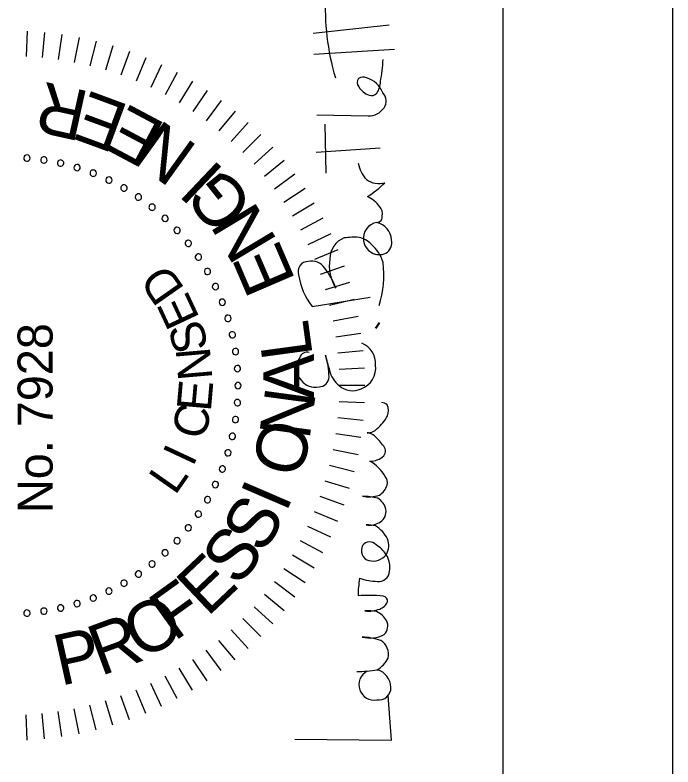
# Model space of a CAD drawing. Extents: x 9916 to 916479, y 6678 to 329942.
# Drawn here: x 916434.26 to 916471.17, y 329764.23 to 329806.42 of the extents above; entities that cross this region are included whole.
import ezdxf

# ---------------------------------------------------------------- set-up
doc = ezdxf.new("R2010")
doc.units = 0
for name, color, linetype in [('Border', 7, 'Continuous'), ('Default', 7, 'Continuous'), ('PLOT BOUNDARY', 7, 'Continuous')]:
    doc.layers.add(name, color=color, linetype=linetype)

# ---------------------------------------------------------------- blocks, each defined once
blk = doc.blocks.new('STAMP')
at = {"layer": 'Default'}
for p, q in [((-0.007955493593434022, 0.0011091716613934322), (-0.007387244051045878, 0.0011370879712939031)), ((0.007955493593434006, 0.0011091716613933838), (0.007387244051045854, 0.0011370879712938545)), ((-0.007926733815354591, 0.0007192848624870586), (-0.007360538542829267, 0.0007750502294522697)), ((0.007926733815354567, 0.0007192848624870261), (0.007360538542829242, 0.0007750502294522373)), ((-0.007878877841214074, 0.0003312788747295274), (-0.0073161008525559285, 0.00041475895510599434)), ((0.007878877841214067, 0.00033127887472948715), (0.00731610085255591, 0.0004147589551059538)), ((-0.007812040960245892, -5.391156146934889e-05), (-0.007254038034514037, 5.708212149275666e-05)), ((0.007812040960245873, -5.3911561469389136e-05), (0.007254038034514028, 5.7082121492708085e-05)), ((-0.0077263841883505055, -0.0004353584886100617), (-0.0071744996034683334, -0.00029711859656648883)), ((0.007726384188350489, -0.0004353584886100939), (0.0071744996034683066, -0.00029711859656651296)), ((-0.007622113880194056, -0.0008121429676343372), (-0.007077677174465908, -0.0006469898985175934)), ((0.0076221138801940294, -0.0008121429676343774), (0.007077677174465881, -0.0006469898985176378)), ((-0.00749948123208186, -0.0011833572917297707), (-0.0069638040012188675, -0.00099168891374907)), ((0.007499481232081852, -0.0011833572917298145), (0.006963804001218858, -0.0009916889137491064)), ((-0.007358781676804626, -0.0015481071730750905), (-0.006833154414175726, -0.001330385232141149)), ((0.007358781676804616, -0.0015481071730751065), (0.006833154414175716, -0.001330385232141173)), ((-0.007200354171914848, -0.0019055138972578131), (-0.006686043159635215, -0.0016622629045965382)), ((0.007200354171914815, -0.0019055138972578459), (0.006686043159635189, -0.0016622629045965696)), ((-0.007024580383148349, -0.0022547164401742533), (-0.0065228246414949, -0.001986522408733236)), ((0.0070245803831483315, -0.0022547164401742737), (0.006522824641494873, -0.001986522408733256)), ((-0.006831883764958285, -0.002594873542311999), (-0.006343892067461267, -0.0023023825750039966)), ((0.006831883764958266, -0.0025948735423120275), (0.006343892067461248, -0.002302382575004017)), ((-0.006622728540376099, -0.002925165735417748), (-0.0061496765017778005, -0.0026090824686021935)), ((0.006622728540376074, -0.002925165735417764), (0.006149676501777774, -0.0026090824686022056)), ((-0.00639761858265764, -0.0032447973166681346), (-0.005940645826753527, -0.0029058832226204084)), ((0.006397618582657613, -0.0032447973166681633), (0.005940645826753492, -0.0029058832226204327)), ((-0.006157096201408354, -0.003552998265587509), (-0.005717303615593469, -0.0031920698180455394)), ((0.006157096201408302, -0.0035529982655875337), (0.005717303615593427, -0.0031920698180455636)), ((-0.005901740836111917, -0.003849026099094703), (-0.005480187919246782, -0.0034669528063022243)), ((0.005901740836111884, -0.0038490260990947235), (0.005480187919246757, -0.0034669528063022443)), ((-0.0056321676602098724, -0.0041321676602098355), (-0.00522986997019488, -0.003729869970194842)), ((0.00563216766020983, -0.0041321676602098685), (0.0052298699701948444, -0.0037298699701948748)), ((-0.005349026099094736, -0.004401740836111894), (-0.004966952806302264, -0.003980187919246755)), ((0.005349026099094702, -0.004401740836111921), (0.004966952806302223, -0.003980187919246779)), ((-0.0050529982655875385, -0.004657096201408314), (-0.004692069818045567, -0.004217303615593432)), ((0.005052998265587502, -0.004657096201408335), (0.004692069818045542, -0.004217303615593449)), ((-0.004744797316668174, -0.0048976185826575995), (-0.004405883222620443, -0.004440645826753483)), ((0.004744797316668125, -0.0048976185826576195), (0.004405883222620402, -0.0044406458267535)), ((-0.0044251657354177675, -0.005122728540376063), (-0.004109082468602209, -0.004649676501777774)), ((0.004425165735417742, -0.00512272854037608), (0.004109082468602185, -0.004649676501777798)), ((-0.004094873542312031, -0.005331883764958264), (-0.0038023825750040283, -0.004843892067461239)), ((0.0040948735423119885, -0.005331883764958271), (0.003802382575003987, -0.004843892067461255)), ((-0.0037547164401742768, -0.005524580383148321), (-0.0034865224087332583, -0.005022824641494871)), ((0.0037547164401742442, -0.005524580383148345), (0.003486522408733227, -0.005022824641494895)), ((-0.003405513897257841, -0.005700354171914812), (-0.0031622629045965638, -0.0051860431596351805)), ((0.0034055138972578, -0.005700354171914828), (0.003162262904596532, -0.005186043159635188)), ((-0.003048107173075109, -0.005858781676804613), (-0.0028303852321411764, -0.005333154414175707)), ((0.003048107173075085, -0.005858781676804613), (0.002830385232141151, -0.005333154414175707)), ((0.00523613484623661, -0.005376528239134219), (0.005338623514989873, -0.0068089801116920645)), ((0.007439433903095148, -0.005319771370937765), (0.0075498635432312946, -0.007129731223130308)), ((0.007905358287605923, -0.005303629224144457), (0.008096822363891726, -0.007011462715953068)), ((-0.0026833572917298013, -0.005999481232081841), (-0.002491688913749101, -0.005463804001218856)), ((0.002683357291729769, -0.005999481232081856), (0.0024916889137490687, -0.005463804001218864)), ((-0.0023121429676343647, -0.006122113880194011), (-0.0021469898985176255, -0.005577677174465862)), ((-0.0019353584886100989, -0.006226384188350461), (-0.0017971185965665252, -0.005674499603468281)), ((0.0019353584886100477, -0.006226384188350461), (0.0017971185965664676, -0.005674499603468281)), ((0.0023121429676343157, -0.006122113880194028), (0.0021469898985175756, -0.005577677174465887)), ((0.004764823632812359, -0.005597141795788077), (0.005863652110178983, -0.005572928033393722)), ((-0.0015539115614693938, -0.006312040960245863), (-0.0014429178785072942, -0.005754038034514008)), ((-0.001168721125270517, -0.006378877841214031), (-0.0010852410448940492, -0.005816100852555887)), ((-0.0007807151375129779, -0.006426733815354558), (-0.0007249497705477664, -0.0058605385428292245)), ((-0.00039082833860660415, -0.006455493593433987), (-0.00036291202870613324, -0.005887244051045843)), ((-2.0539125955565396e-17, -0.006465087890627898), (-2.0539125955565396e-17, -0.005896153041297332)), ((0.0003908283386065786, -0.0064554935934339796), (0.0003629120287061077, -0.005887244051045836)), ((0.0007807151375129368, -0.006426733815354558), (0.0007249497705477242, -0.005860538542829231)), ((0.0011687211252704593, -0.006378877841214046), (0.0010852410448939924, -0.005816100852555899)), ((0.0015539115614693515, -0.006312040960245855), (0.0014429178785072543, -0.005754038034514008)), ((0.001282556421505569, -0.006716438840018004), (0.001411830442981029, -0.006805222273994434)), ((0.0012888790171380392, -0.0067038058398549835), (0.0014181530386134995, -0.006792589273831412))]:
    blk.add_line(p, q, dxfattribs=at)
for points in [[(-0.007938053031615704, -0.004895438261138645), (-0.007956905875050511, -0.007061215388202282), (-0.0069577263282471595, -0.006985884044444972)], [(0.0017747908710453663, -0.005281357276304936), (0.001982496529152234, -0.006583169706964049)], [(0.006077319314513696, -0.005389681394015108), (0.006050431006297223, -0.00653989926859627)]]:
    blk.add_lwpolyline(points, dxfattribs=at)
for centre, radius, start, end in [((-0.005106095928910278, 0.0011173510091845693), 7.111685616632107e-05, 94.28571428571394, 274.28571428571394), ((-0.005106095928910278, 0.0011173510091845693), 7.11168561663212e-05, 274.28571428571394, 94.28571428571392), ((0.005106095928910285, 0.0011173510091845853), 7.11168561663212e-05, 85.71428571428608, 265.71428571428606), ((0.005106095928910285, 0.0011173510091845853), 7.11168561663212e-05, 265.71428571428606, 85.71428571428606), ((-0.005063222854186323, 0.0007368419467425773), 7.111685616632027e-05, 98.5714285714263, 278.5714285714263), ((-0.005063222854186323, 0.0007368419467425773), 7.111685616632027e-05, 278.5714285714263, 98.5714285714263), ((0.005063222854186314, 0.0007368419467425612), 7.111685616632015e-05, 81.42857142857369, 261.4285714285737), ((0.005063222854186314, 0.0007368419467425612), 7.111685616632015e-05, 261.4285714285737, 81.42857142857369), ((-0.0049920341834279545, 0.00036060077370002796), 7.11168561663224e-05, 102.8571428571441, 282.8571428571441), ((-0.0049920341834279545, 0.00036060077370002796), 7.11168561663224e-05, 282.8571428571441, 102.85714285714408), ((0.004992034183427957, 0.00036060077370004), 7.111685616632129e-05, 77.14285714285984, 257.14285714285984), ((0.004992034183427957, 0.00036060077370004), 7.111685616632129e-05, 257.14285714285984, 77.14285714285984), ((-0.004892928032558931, -9.26841668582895e-06), 7.111685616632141e-05, 107.14285714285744, 287.14285714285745), ((-0.004892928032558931, -9.26841668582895e-06), 7.111685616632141e-05, 287.14285714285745, 107.14285714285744), ((0.004892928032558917, -9.268416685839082e-06), 7.111685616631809e-05, 72.85714285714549, 252.8571428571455), ((0.004892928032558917, -9.268416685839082e-06), 7.111685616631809e-05, 252.85714285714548, 72.85714285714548), ((-0.004766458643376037, -0.00037069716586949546), 7.111685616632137e-05, 111.42857142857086, 291.4285714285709), ((-0.004766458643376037, -0.00037069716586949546), 7.111685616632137e-05, 291.4285714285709, 111.42857142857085), ((0.0047664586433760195, -0.00037069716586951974), 7.111685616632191e-05, 68.57142857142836, 248.57142857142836), ((0.0047664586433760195, -0.00037069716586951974), 7.111685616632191e-05, 248.57142857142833, 68.57142857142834), ((-0.0046133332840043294, -0.0007216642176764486), 7.1116856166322e-05, 115.71428571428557, 295.71428571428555), ((-0.0046133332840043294, -0.0007216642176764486), 7.1116856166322e-05, 295.71428571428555, 115.71428571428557), ((0.0046133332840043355, -0.0007216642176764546), 7.111685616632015e-05, 64.28571428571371, 244.2857142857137), ((0.0046133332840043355, -0.0007216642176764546), 7.111685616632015e-05, 244.2857142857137, 64.2857142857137), ((-0.004434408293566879, -0.0010602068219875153), 7.111685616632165e-05, 119.99999999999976, 299.9999999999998), ((-0.004434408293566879, -0.0010602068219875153), 7.111685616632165e-05, 299.9999999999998, 119.99999999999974), ((0.00443440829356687, -0.0010602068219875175), 7.111685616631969e-05, 59.99999999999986, 239.99999999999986), ((0.00443440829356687, -0.0010602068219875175), 7.111685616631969e-05, 239.99999999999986, 59.99999999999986), ((-0.004230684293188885, -0.0013844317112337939), 7.111685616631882e-05, 124.28571428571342, 304.2857142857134), ((-0.004230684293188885, -0.0013844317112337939), 7.111685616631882e-05, 304.2857142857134, 124.28571428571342), ((0.004230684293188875, -0.0013844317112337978), 7.111685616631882e-05, 55.714285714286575, 235.71428571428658), ((0.004230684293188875, -0.0013844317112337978), 7.111685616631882e-05, 235.71428571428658, 55.714285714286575), ((-0.004003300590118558, -0.0016925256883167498), 7.111685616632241e-05, 128.57142857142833, 308.5714285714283), ((-0.004003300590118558, -0.0016925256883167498), 7.111685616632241e-05, 308.5714285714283, 128.57142857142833), ((0.004003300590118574, -0.0016925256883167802), 7.111685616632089e-05, 51.42857142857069, 231.4285714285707), ((0.004003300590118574, -0.0016925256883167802), 7.111685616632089e-05, 231.42857142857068, 51.42857142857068), ((-0.003753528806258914, -0.0019827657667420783), 7.11168561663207e-05, 132.85714285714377, 312.8571428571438), ((-0.003753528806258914, -0.0019827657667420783), 7.11168561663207e-05, 312.85714285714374, 132.85714285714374), ((0.003753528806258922, -0.0019827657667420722), 7.111685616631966e-05, 47.14285714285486, 227.14285714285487), ((0.003753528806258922, -0.0019827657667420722), 7.111685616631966e-05, 227.14285714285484, 47.14285714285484), ((-0.0034827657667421, -0.002253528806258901), 7.111685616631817e-05, 317.1428571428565, 137.14285714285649), ((0.0034827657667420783, -0.0022535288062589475), 7.111685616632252e-05, 42.857142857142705, 222.85714285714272), ((-0.0034827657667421, -0.002253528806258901), 7.111685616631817e-05, 137.14285714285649, 317.1428571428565), ((0.0034827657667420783, -0.0022535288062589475), 7.111685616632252e-05, 222.8571428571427, 42.85714285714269), ((-0.0031925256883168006, -0.0025033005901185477), 7.111685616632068e-05, 141.42857142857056, 321.42857142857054), ((-0.0031925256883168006, -0.0025033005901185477), 7.111685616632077e-05, 321.42857142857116, 141.4285714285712), ((0.0031925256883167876, -0.002503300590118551), 7.111685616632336e-05, 38.57142857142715, 218.57142857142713), ((0.0031925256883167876, -0.002503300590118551), 7.111685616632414e-05, 218.57142857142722, 38.57142857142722), ((-0.0028844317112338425, -0.0027306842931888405), 7.111685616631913e-05, 145.7142857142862, 325.71428571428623), ((-0.0028844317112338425, -0.0027306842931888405), 7.111685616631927e-05, 325.7142857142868, 145.71428571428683), ((0.002884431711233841, -0.0027306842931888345), 7.111685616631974e-05, 34.28571428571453, 214.28571428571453), ((0.002884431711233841, -0.0027306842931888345), 7.111685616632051e-05, 214.28571428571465, 34.28571428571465), ((-0.0025602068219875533, -0.0029344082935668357), 7.111685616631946e-05, 329.9999999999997, 149.99999999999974), ((0.0025602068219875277, -0.0029344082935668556), 7.111685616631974e-05, 30.000000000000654, 210.00000000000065), ((-0.0025602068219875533, -0.0029344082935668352), 7.111685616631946e-05, 149.99999999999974, 329.9999999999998), ((0.0025602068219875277, -0.002934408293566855), 7.111685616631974e-05, 210.00000000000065, 30.000000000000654), ((-0.0022216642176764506, -0.0031133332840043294), 7.111685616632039e-05, 154.2857142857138, 334.28571428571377), ((-0.0022216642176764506, -0.0031133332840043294), 7.111685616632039e-05, 334.2857142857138, 154.2857142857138), ((-0.0018706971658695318, -0.0032664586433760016), 7.111685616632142e-05, 338.57142857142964, 158.57142857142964), ((0.0018706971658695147, -0.0032664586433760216), 7.111685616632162e-05, 21.428571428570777, 201.42857142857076), ((0.0022216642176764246, -0.0031133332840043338), 7.111685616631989e-05, 25.714285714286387, 205.71428571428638), ((0.0022216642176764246, -0.0031133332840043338), 7.111685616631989e-05, 205.71428571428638, 25.714285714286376), ((-0.0018706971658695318, -0.003266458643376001), 7.111685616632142e-05, 158.57142857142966, 338.5714285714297), ((-0.0015092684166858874, -0.003392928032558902), 7.111685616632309e-05, 162.85714285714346, 342.85714285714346), ((-0.0015092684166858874, -0.003392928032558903), 7.111685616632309e-05, 342.85714285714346, 162.85714285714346), ((0.0015092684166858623, -0.0033929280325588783), 7.111685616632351e-05, 17.142857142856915, 197.1428571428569), ((0.0015092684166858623, -0.0033929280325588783), 7.111685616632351e-05, 197.1428571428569, 17.14285714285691), ((0.0018706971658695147, -0.0032664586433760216), 7.111685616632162e-05, 201.42857142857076, 21.428571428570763), ((-0.0011393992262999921, -0.0034920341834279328), 7.111685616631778e-05, 167.14285714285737, 347.14285714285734), ((-0.0011393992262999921, -0.0034920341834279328), 7.111685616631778e-05, 347.14285714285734, 167.14285714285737), ((-0.0007631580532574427, -0.003563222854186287), 7.111685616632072e-05, 351.4285714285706, 171.4285714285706), ((-0.0003826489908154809, -0.003606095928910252), 7.111685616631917e-05, 355.7142857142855, 175.7142857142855), ((0.0003826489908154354, -0.0036060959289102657), 7.111685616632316e-05, 4.285714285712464, 184.28571428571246), ((0.0007631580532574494, -0.0035632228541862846), 7.111685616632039e-05, 8.571428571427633, 188.57142857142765), ((0.0011393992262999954, -0.0034920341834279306), 7.111685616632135e-05, 12.857142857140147, 192.85714285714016), ((0.0011393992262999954, -0.0034920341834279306), 7.111685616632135e-05, 192.85714285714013, 12.857142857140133), ((-0.0007631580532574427, -0.003563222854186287), 7.111685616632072e-05, 171.4285714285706, 351.4285714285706), ((-0.0003826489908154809, -0.003606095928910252), 7.111685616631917e-05, 175.71428571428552, 355.71428571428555), ((-1.2628786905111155e-17, -0.0036204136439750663), 7.111685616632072e-05, 0, 180), ((-1.2628786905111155e-17, -0.0036204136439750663), 7.111685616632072e-05, 180, 0), ((0.0003826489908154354, -0.0036060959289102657), 7.111685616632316e-05, 184.28571428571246, 4.285714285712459), ((0.0007631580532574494, -0.0035632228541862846), 7.111685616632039e-05, 188.57142857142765, 8.571428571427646), ((0.00036114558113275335, -0.0053488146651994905), 0.0003972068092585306, 127.45926190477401, 192.9614203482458), ((0.00039604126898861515, -0.005375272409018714), 0.00043958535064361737, 57.64755033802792, 128.97245422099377), ((0.0005805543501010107, -0.005165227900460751), 0.00016909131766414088, 342.3611945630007, 72.54487353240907), ((0.0027009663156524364, -0.006477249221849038), 0.001512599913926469, 98.17812986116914, 127.75649827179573), ((0.0025607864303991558, -0.005191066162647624), 0.0002239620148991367, 359.61429023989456, 109.56218572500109), ((0.0024288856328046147, -0.00526578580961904), 0.0003633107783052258, 304.8740098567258, 11.625468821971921), ((0.00019608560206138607, -0.005439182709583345), 0.0002220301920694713, 179.67057284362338, 269.694601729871), ((0.0015502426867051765, -0.00415818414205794), 0.0017765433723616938, 290.99837671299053, 307.69878588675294), ((0.0004564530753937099, -0.0062299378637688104), 0.0005678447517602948, 102.0773813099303, 143.39383108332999), ((0.00015503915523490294, -0.003868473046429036), 0.001793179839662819, 271.2738092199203, 287.01217780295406), ((0.002166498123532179, -0.011827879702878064), 0.006419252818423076, 103.3923944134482, 106.55297850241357), ((0.0026896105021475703, -0.006582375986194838), 0.0009159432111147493, 80.29637939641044, 123.29138431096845), ((0.0028457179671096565, -0.006179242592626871), 0.0004997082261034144, 20.58705533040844, 90.19763829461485), ((0.008493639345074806, -0.011221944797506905), 0.00564567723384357, 87.11335107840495, 106.33073943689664), ((0.00031613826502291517, -0.006186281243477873), 0.0004319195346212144, 136.9297266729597, 206.7934360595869), ((0.0014539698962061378, -0.006245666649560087), 0.0018752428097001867, 357.2040173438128, 7.418903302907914), ((-0.00671307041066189, -0.006678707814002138), 0.0003465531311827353, 28.430349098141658, 189.68707560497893), ((-0.003955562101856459, -0.006312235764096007), 0.002461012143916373, 179.30402472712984, 190.0665804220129), ((-0.007040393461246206, -0.006369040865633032), 0.0013973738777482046, 341.03759348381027, 358.5906169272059), ((-0.004987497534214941, -0.006577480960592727), 0.0006786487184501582, 165.1377733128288, 207.96825790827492), ((-0.007015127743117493, -0.0065631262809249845), 0.0023079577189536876, 352.1195763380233, 6.249520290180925), ((-0.004786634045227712, -0.009314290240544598), 0.003003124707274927, 81.15725195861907, 88.74550427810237), ((-0.002857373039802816, -0.006810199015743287), 0.001539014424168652, 162.47862001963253, 177.5735090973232), ((-0.0037000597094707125, -0.006623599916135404), 0.00023723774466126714, 61.91684207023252, 163.66717131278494), ((-0.00388024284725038, -0.006412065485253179), 0.0013948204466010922, 345.72048696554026, 0.12433676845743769), ((-0.0016914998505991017, -0.006545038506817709), 0.0008054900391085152, 170.27954956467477, 197.78532003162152), ((0.0003962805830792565, -0.006217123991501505), 0.0004936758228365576, 199.38474076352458, 277.55079490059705), ((0.0004891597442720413, -0.006207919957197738), 0.0004993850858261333, 266.784921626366, 337.7362429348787), ((0.0027994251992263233, -0.006216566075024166), 0.0005411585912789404, 313.71200852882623, 347.12598992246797), ((0.005109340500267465, -0.0069995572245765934), 0.000693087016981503, 99.83623703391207, 134.2279465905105), ((0.006942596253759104, -0.006719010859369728), 0.000455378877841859, 120.67649823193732, 159.39228314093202), ((0.006803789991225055, -0.00643536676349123), 0.00014287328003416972, 52.527438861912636, 130.8886473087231), ((0.00673895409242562, -0.006426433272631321), 0.0001842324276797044, 335.7048269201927, 34.54029227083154), ((-0.006329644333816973, -0.006519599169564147), 0.0012732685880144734, 350.5388137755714, 2.446920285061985), ((-0.004310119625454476, -0.006538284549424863), 0.0007509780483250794, 174.41813129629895, 200.30191948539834), ((-0.0035430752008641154, -0.006644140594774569), 0.0003944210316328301, 167.2189950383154, 230.16055614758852), ((-0.0037052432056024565, -0.0065716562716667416), 0.0001960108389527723, 312.7382758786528, 53.40100716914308), ((-0.003974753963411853, -0.006503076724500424), 0.0008496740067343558, 346.26214121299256, 0.7257075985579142), ((-0.002682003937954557, -0.006568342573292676), 0.00044961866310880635, 170.2648919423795, 213.2954708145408), ((-0.002536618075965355, -0.006083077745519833), 0.0009765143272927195, 300.6803608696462, 329.51258202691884), ((-0.0012666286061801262, -0.006594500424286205), 0.00042878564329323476, 177.86300386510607, 223.17874837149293), ((-0.0013865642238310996, -0.006474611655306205), 0.0003320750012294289, 327.8843366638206, 353.1980671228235), ((-0.0008025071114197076, -0.006544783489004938), 0.0002561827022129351, 173.08541670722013, 230.55848375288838), ((0.0032953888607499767, -0.006791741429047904), 0.00035634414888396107, 97.37079091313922, 203.8922211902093), ((0.0033059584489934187, -0.006794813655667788), 0.0003608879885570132, 9.655140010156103, 98.97262191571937), ((0.003588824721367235, -0.00621969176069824), 0.0007209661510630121, 306.1913846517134, 335.23134174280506), ((0.005998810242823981, -0.005456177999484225), 0.0020534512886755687, 211.2594929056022, 225.2513717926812), ((0.004994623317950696, -0.006780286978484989), 0.0004614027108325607, 143.047197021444, 196.91634387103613), ((0.006484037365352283, -0.0065437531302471), 0.0004336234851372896, 179.49077270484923, 234.71689370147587), ((0.006664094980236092, -0.006611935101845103), 0.00015702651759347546, 160.1953187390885, 230.79232729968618), ((0.006346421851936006, -0.006330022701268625), 0.0005863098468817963, 292.72445583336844, 342.91922299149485), ((-0.006777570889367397, -0.006772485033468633), 0.00027937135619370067, 172.70712454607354, 271.16395527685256), ((-0.006783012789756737, -0.006633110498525), 0.0004188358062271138, 271.5209447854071, 344.87406906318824), ((-0.005754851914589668, -0.006345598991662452), 0.0007393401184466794, 212.4592088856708, 240.63114206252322), ((-0.0055308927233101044, -0.006522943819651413), 0.0005014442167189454, 301.1133493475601, 335.74975916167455), ((-0.004152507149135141, -0.006775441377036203), 0.00024439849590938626, 172.85451562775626, 266.8151593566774), ((-0.00421927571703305, -0.006314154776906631), 0.0007614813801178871, 303.79189499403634, 328.18256979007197), ((-0.0038004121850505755, -0.006299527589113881), 0.000766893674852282, 298.0105046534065, 328.09350966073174), ((-0.0020051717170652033, -0.0059200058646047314), 0.0011594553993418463, 305.5205731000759, 320.90595982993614), ((-0.0001785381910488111, -0.0060637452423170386), 0.0010391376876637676, 220.79179678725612, 241.16030041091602), ((0.002532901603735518, -0.0060711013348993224), 0.0008355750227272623, 286.05704557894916, 320.0421489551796), ((0.0032445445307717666, -0.006637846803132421), 0.00042819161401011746, 273.5716384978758, 346.98387133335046), ((0.0037841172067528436, -0.006733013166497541), 0.00012238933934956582, 180.59606692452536, 282.14231124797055), ((0.006821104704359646, -0.0063671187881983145), 0.0004472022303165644, 235.03647869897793, 269.9466508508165), ((-0.006036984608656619, -0.006622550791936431), 0.0003760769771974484, 257.6460165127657, 327.7710077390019), ((-0.005391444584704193, -0.006712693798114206), 0.0002677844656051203, 223.12676578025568, 296.5429712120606), ((-0.004715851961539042, -0.006689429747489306), 0.00031800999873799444, 200.1253724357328, 244.48124886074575), ((-0.004842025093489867, -0.006862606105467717), 0.00011432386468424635, 264.56536252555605, 351.47104640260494), ((-0.0028340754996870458, -0.006679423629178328), 0.00026169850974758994, 211.24435430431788, 280.94854976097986), ((-0.00285343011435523, -0.006566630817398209), 0.0003761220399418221, 280.5798823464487, 329.7517392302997), ((-0.0021179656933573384, -0.00658432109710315), 0.00039838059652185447, 211.26450698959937, 253.32703764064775), ((-0.0014677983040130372, -0.006749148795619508), 0.0001780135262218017, 231.21384232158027, 319.94914487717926), ((-0.0005623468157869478, -0.006834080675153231), 0.00018159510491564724, 314.66347430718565, 358.2957841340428), ((0.0024869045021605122, -0.0045618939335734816), 0.0023287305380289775, 252.701645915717, 276.8342307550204), ((0.0038601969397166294, -0.006618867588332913), 0.000239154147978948, 257.8497316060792, 310.1947013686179), ((0.006385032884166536, -0.006654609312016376), 0.00028643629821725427, 238.07646434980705, 310.98972037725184), ((0.007377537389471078, -0.004287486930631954), 0.0025874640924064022, 257.5721309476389, 268.73466328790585), ((-0.00407546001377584, -0.006500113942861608), 0.0005271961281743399, 260.1016649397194, 302.042575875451), ((-0.0035868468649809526, -0.00658750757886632), 0.00041578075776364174, 239.8376850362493, 290.64484911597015), ((-0.0021804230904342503, -0.006741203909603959), 0.00023065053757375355, 257.01114107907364, 308.02112433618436), ((-0.0005688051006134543, -0.006705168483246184), 0.00029083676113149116, 247.5695171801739, 297.4590386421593), ((0.003211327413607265, -0.006788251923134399), 0.0002833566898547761, 211.44349084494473, 282.2024112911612)]:
    blk.add_arc(centre, radius, start, end, dxfattribs=at)
for s, height, p in [('No. 7928', 0.0007851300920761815, (-0.002860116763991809, 0.0005420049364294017)), ('A', 0.0011378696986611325, (-0.0003007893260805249, -0.005327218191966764))]:
    blk.add_text(s, height=height, dxfattribs=at).set_placement(p)
for s, height, rotation, p in [('R', 0.001137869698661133, 77.5, (0.006589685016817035, -0.0003191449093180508)), ('P', 0.0011378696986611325, 282.5, (-0.006741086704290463, 0.00036378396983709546)), ('E', 0.0011378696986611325, 69.75, (0.006276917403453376, -0.001210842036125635)), ('R', 0.0011378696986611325, 290.25, (-0.00652629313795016, -0.0005348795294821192)), ('E', 0.0011378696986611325, 62, (0.005854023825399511, -0.002032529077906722)), ('O', 0.0011378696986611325, 298, (-0.006169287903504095, -0.0014396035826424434)), ('N', 0.001137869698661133, 54.25000000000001, (0.005352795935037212, -0.0027499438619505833)), ('F', 0.001137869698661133, 305.75, (-0.0057573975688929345, -0.002187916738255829)), ('L', 0.0007680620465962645, 324.99999999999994, (-0.002479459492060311, -0.00220631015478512)), ('D', 0.0007680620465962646, 34.99999999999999, (0.002169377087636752, -0.0024365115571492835)), ('E', 0.0007680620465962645, 25.000000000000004, (0.001513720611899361, -0.002766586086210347)), ('I', 0.0007680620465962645, 335, (-0.001841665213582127, -0.002604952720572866)), ('C', 0.0007680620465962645, 345, (-0.0012469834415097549, -0.0028524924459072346)), ('S', 0.0007680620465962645, 14.999999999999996, (0.0008506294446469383, -0.0029637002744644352)), ('E', 0.0011378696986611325, 313.5, (-0.005207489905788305, -0.0029306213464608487)), ('E', 0.0007680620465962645, 355, (-0.0005969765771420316, -0.00300722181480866)), ('N', 0.0007680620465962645, 5, (0.0001499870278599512, -0.003047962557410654)), ('I', 0.001137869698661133, 46.499999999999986, (0.004817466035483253, -0.003341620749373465)), ('G', 0.001137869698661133, 38.750000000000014, (0.004038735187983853, -0.004012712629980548)), ('S', 0.0011378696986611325, 321.25, (-0.004535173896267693, -0.0036142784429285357)), ('N', 0.0011378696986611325, 30.999999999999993, (0.0032404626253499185, -0.004517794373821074)), ('S', 0.0011378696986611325, 328.99999999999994, (-0.003804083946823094, -0.004179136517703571)), ('E', 0.0011378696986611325, 23.249999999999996, (0.0023543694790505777, -0.004919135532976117)), ('I', 0.0011378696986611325, 336.75, (-0.0028749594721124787, -0.00469547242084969)), ('O', 0.001137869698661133, 344.5, (-0.0021143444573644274, -0.004998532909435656)), ('N', 0.001137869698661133, 352.25, (-0.001239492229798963, -0.005221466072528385)), ('L', 0.001137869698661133, 7.75, (0.0006711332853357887, -0.0052988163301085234))]:
    blk.add_text(s, height=height, rotation=rotation, dxfattribs=at).set_placement(p)

msp = doc.modelspace()

# ---------------------------------------------------------------- linework, layer by layer
at = {"layer": 'Border'}
msp.add_line((916461.6361139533, 329407.0108995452), (916461.6361139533, 329932.0098495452), dxfattribs=at)
at = {"layer": 'PLOT BOUNDARY'}
msp.add_lwpolyline([(915621.171063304, 329391.7003663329), (916471.169363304, 329391.7003663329), (916471.169363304, 329941.6992663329), (915621.171063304, 329941.6992663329)], close=True, dxfattribs=at)

# ---------------------------------------------------------------- block references
at = {"layer": 'Border', "xscale": 2499.999999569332, "yscale": 2499.999999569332, "rotation": 90}
msp.add_blockref('STAMP', (916437.7218680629, 329785.62897801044), dxfattribs=at)

doc.saveas('drawing.dxf')
